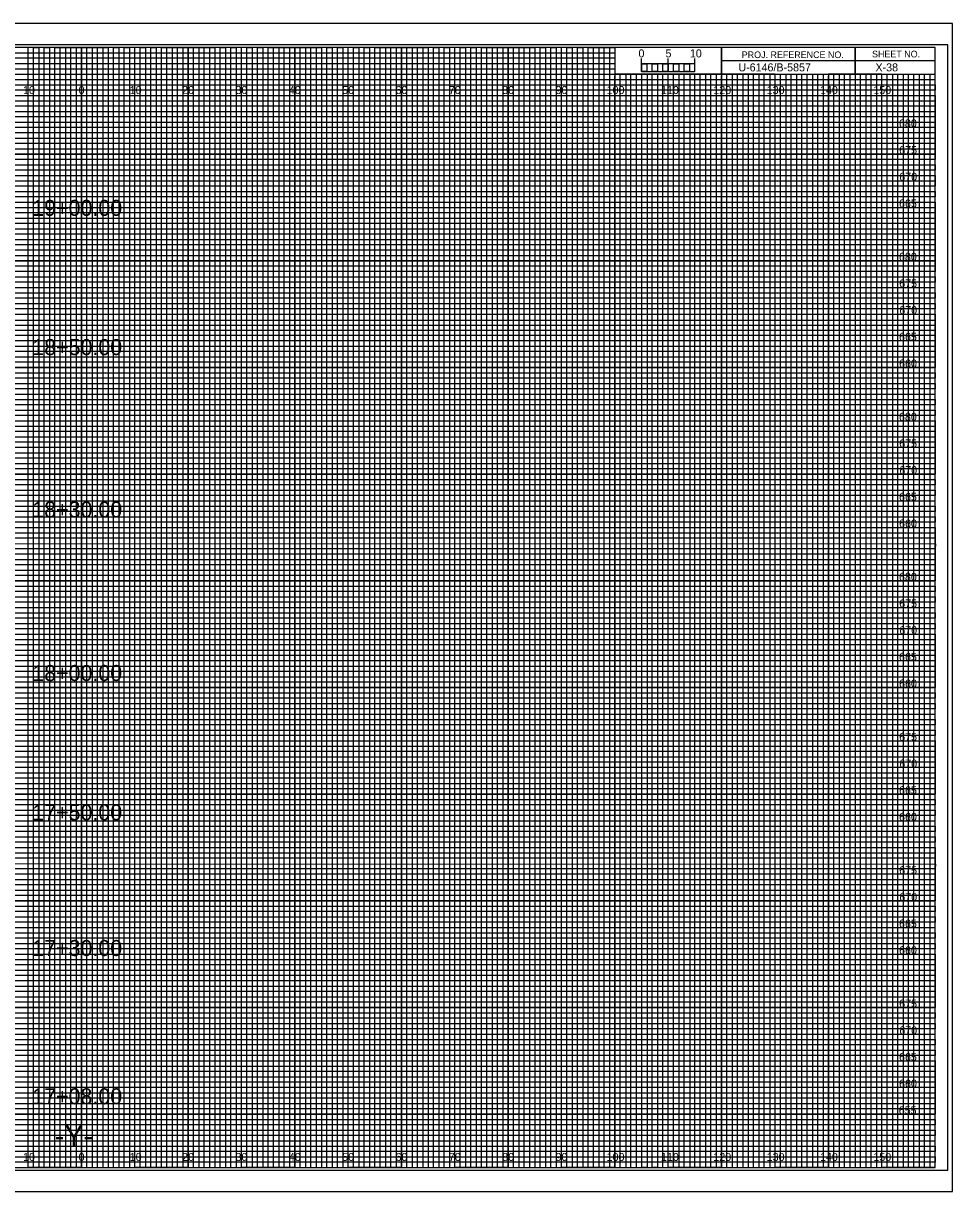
# Model space of a CAD drawing. Extents: x -13 to 323, y 655 to 874.
# Drawn here: x 149.1 to 323.3, y 655.5 to 874.5 of the extents above; entities that cross this region are included whole.
import ezdxf

# ---------------------------------------------------------------- set-up
doc = ezdxf.new("R2010")
doc.units = 0
for name, color, linetype in [('Exist Cross Section Cell', 7, 'Continuous'), ('Exist XS Center Line Elevation Label', 7, 'Continuous'), ('Exist XS Ground Line', 7, 'Continuous'), ('Prop XS Dump Level', 7, 'Continuous'), ('Prop XS EOT Tick Mark', 7, 'Continuous'), ('Prop XS Finish Grade', 7, 'Continuous'), ('Prop XS Finish Grade CurbGutter', 7, 'Continuous'), ('Prop XS Finish Grade Earthwork', 7, 'Continuous'), ('Prop XS Finish Grade Pavement', 7, 'Continuous'), ('Prop XS Hydro Elevations', 7, 'Continuous'), ('Prop XS Pvmt Edge Slope', 7, 'Continuous'), ('Prop XS SE Text', 7, 'Continuous'), ('Prop XS Side Slope Text', 7, 'Continuous'), ('Prop XS SS Elevation Text', 7, 'Continuous'), ('Prop XS Subgrade CurbGutter', 7, 'Continuous'), ('Prop XS Subgrade Earthwork', 7, 'Continuous'), ('Scratch_Level_3', 7, 'Continuous')]:
    doc.layers.add(name, color=color, linetype=linetype)

msp = doc.modelspace()

# ---------------------------------------------------------------- linework, layer by layer
at = {"layer": 'Exist Cross Section Cell'}
for points in [[(145, 660), (155, 660), (155, 870), (165, 870), (165, 660), (175, 660), (175, 870), (185, 870), (185, 660), (195, 660), (195, 870), (205, 870), (205, 660), (215, 660), (215, 870), (225, 870), (225, 660), (235, 660), (235, 870), (245, 870), (245, 660), (255, 660), (255, 870), (259.93, 870), (260, 870), (260, 865), (264.99, 865), (264.99, 660), (275, 660), (275, 865), (285, 865), (285, 660), (295, 660), (295, 865), (305, 865), (305, 660), (315, 660), (315, 865)], [(0, 865), (275, 865)], [(0, 845), (320, 845), (320, 855), (0, 855)], [(0, 825), (320, 825), (320, 835), (0, 835)], [(0, 805), (320, 805), (320, 815), (0, 815)], [(0, 785), (320, 785), (320, 795), (0, 795)], [(0, 765), (320, 765), (320, 775), (0, 775)], [(0, 745), (320, 745), (320, 755), (0, 755)], [(0, 725), (320, 725), (320, 735), (0, 735)], [(0, 705), (320, 705), (320, 715), (0, 715)], [(0, 685), (320, 685), (320, 695), (0, 695)], [(0, 665), (320, 665), (320, 675), (0, 675)]]:
    msp.add_lwpolyline(points, dxfattribs=at)
at = {"layer": 'Exist XS Center Line Elevation Label'}
for p, q in [((150, 870), (140, 870)), ((150, 660), (150, 870)), ((170, 870), (160, 870)), ((160, 870), (160, 660)), ((170, 660), (170, 870)), ((190, 870), (180, 870)), ((180, 870), (180, 660)), ((190, 660), (190, 870)), ((210, 870), (200, 870)), ((200, 870), (200, 660)), ((210, 660), (210, 870)), ((230, 870), (220, 870)), ((220, 870), (220, 660)), ((230, 660), (230, 870)), ((250, 870), (240, 870)), ((240, 870), (240, 660)), ((250, 660), (250, 870)), ((260, 870), (260, 660)), ((270, 660), (270, 865)), ((290, 865), (280, 865)), ((280, 865), (280, 660)), ((290, 660), (290, 865)), ((310, 865), (300, 865)), ((300, 865), (300, 660)), ((310, 660), (310, 865)), ((160, 660), (150, 660)), ((180, 660), (170, 660)), ((200, 660), (190, 660)), ((220, 660), (210, 660)), ((240, 660), (230, 660)), ((260, 660), (250, 660)), ((280, 660), (270, 660)), ((300, 660), (290, 660)), ((320, 660), (310, 660)), ((320, 660), (320, 660))]:
    msp.add_line(p, q, dxfattribs=at)
for points in [[(0, 860), (320, 860), (320, 850), (0, 850)], [(0, 840), (320, 840), (320, 830), (0, 830)], [(0, 820), (320, 820), (320, 810), (0, 810)], [(0, 800), (320, 800), (320, 790), (0, 790)], [(0, 780), (320, 780), (320, 770), (0, 770)], [(0, 760), (320, 760), (320, 750), (0, 750)], [(0, 740), (320, 740), (320, 730), (0, 730)], [(0, 720), (320, 720), (320, 710), (0, 710)], [(0, 700), (320, 700), (320, 690), (0, 690)], [(0, 680), (320, 680), (320, 670), (0, 670)]]:
    msp.add_lwpolyline(points, dxfattribs=at)
at = {"layer": 'Prop XS Dump Level'}
for p, q in [((305, 870), (305, 865)), ((305, 865), (305, 870)), ((280, 867.5), (280, 865)), ((320, 867.49), (280, 867.49)), ((280, 865), (320, 865))]:
    msp.add_line(p, q, dxfattribs=at)
for points in [[(320, 870), (0, 870), (0, 660), (320, 660)], [(280, 870), (260, 870), (260, 865.03), (280, 865.03)], [(320, 870), (280, 870), (280, 865), (320, 865)]]:
    msp.add_lwpolyline(points, close=True, dxfattribs=at)
at = {"layer": 'Prop XS Finish Grade Earthwork'}
for p, q in [((150, 660), (150, 870)), ((160, 660), (160, 870)), ((170, 660), (170, 870)), ((180, 660), (180, 870)), ((190, 660), (190, 870)), ((200, 660), (200, 870)), ((210, 660), (210, 870)), ((220, 660), (220, 870)), ((230, 660), (230, 870)), ((240, 660), (240, 870)), ((250, 660), (250, 870)), ((260, 660), (260, 864.69)), ((270, 660), (270, 864.69)), ((280, 660), (280, 864.69)), ((290, 660), (290, 864.69)), ((300, 660), (300, 864.69)), ((310, 660), (310, 864.69)), ((0, 860), (320, 860)), ((0, 850), (320, 850)), ((0, 840), (320, 840)), ((0, 830), (320, 830)), ((0, 820), (320, 820)), ((0, 810), (320, 810)), ((0, 800), (320, 800)), ((0, 790), (320, 790)), ((0, 780), (320, 780)), ((0, 770), (320, 770)), ((0, 760), (320, 760)), ((0, 750), (320, 750)), ((0, 740), (320, 740)), ((0, 730), (320, 730)), ((0, 720), (320, 720)), ((0, 710), (320, 710)), ((0, 700), (320, 700)), ((0, 690), (320, 690)), ((0, 680), (320, 680)), ((0, 670), (320, 670))]:
    msp.add_line(p, q, dxfattribs=at)
at = {"layer": 'Prop XS Hydro Elevations'}
for p, q in [((265, 865.49), (265, 867.9)), ((265, 866.9), (265, 867.9)), ((270, 865.49), (270, 867.9)), ((275, 865.49), (275, 867.9)), ((275, 866.9), (275, 867.9))]:
    msp.add_line(p, q, dxfattribs=at)
for points in [[(275, 866.9), (265, 866.9), (265, 865.49), (275, 865.49)], [(265, 866.9), (266, 866.9), (266, 865.49), (265, 865.49)], [(267, 866.9), (268, 866.9), (268, 865.49), (267, 865.49)], [(269, 866.9), (270, 866.9), (270, 865.49), (269, 865.49)], [(271, 866.9), (272, 866.9), (272, 865.49), (271, 865.49)], [(273, 866.9), (274, 866.9), (274, 865.49), (273, 865.49)]]:
    msp.add_lwpolyline(points, close=True, dxfattribs=at)
at = {"layer": 'Prop XS Pvmt Edge Slope'}
for p, q in [((323.3, 874.5), (-13.4, 874.5)), ((-13.4, 655.5), (323.3, 655.5))]:
    msp.add_line(p, q, dxfattribs=at)
at = {"layer": 'Prop XS SE Text'}
for p, q in [((267, 865), (266.01, 865)), ((266.01, 865), (266.01, 660)), ((267, 660), (267, 865)), ((269, 865), (268, 865)), ((268, 865), (268, 660)), ((269, 660), (269, 865)), ((266.01, 660), (265, 660)), ((268, 660), (267, 660))]:
    msp.add_line(p, q, dxfattribs=at)
for points in [[(150, 660), (151, 660), (151, 870), (152, 870), (152, 660)], [(152, 660), (153, 660), (153, 870), (154, 870), (154, 660)], [(155, 660), (156, 660), (156, 870), (157, 870), (157, 660)], [(157, 660), (158, 660), (158, 870), (159, 870), (159, 660)], [(160, 660), (161, 660), (161, 870), (162, 870), (162, 660)], [(162, 660), (163, 660), (163, 870), (164, 870), (164, 660)], [(165, 660), (166, 660), (166, 870), (167, 870), (167, 660)], [(167, 660), (168, 660), (168, 870), (169, 870), (169, 660)], [(170, 660), (171, 660), (171, 870), (172, 870), (172, 660)], [(172, 660), (173, 660), (173, 870), (174, 870), (174, 660)], [(175, 660), (176, 660), (176, 870), (177, 870), (177, 660)], [(177, 660), (178, 660), (178, 870), (179, 870), (179, 660)], [(180, 660), (181, 660), (181, 870), (182, 870), (182, 660)], [(182, 660), (183, 660), (183, 870), (184, 870), (184, 660)], [(185, 660), (186, 660), (186, 870), (187, 870), (187, 660)], [(187, 660), (188, 660), (188, 870), (189, 870), (189, 660)], [(190, 660), (191, 660), (191, 870), (192, 870), (192, 660)], [(192, 660), (193, 660), (193, 870), (194, 870), (194, 660)], [(195, 660), (196, 660), (196, 870), (197, 870), (197, 660)], [(197, 660), (198, 660), (198, 870), (199, 870), (199, 660)], [(200, 660), (201, 660), (201, 870), (202, 870), (202, 660)], [(202, 660), (203, 660), (203, 870), (204, 870), (204, 660)], [(205, 660), (206, 660), (206, 870), (207, 870), (207, 660)], [(207, 660), (208, 660), (208, 870), (209, 870), (209, 660)], [(210, 660), (211, 660), (211, 870), (212, 870), (212, 660)], [(212, 660), (213, 660), (213, 870), (214, 870), (214, 660)], [(215, 660), (216, 660), (216, 870), (217, 870), (217, 660)], [(217, 660), (218, 660), (218, 870), (219, 870), (219, 660)], [(220, 660), (221, 660), (221, 870), (222, 870), (222, 660)], [(222, 660), (223, 660), (223, 870), (224, 870), (224, 660)], [(225, 660), (226, 660), (226, 870), (227, 870), (227, 660)], [(227, 660), (228, 660), (228, 870), (229, 870), (229, 660)], [(230, 660), (231, 660), (231, 870), (232, 870), (232, 660)], [(232, 660), (233, 660), (233, 870), (234, 870), (234, 660)], [(235, 660), (236, 660), (236, 870), (237, 870), (237, 660)], [(237, 660), (238, 660), (238, 870), (239, 870), (239, 660)], [(240, 660), (241, 660), (241, 870), (242, 870), (242, 660)], [(242, 660), (243, 660), (243, 870), (244, 870), (244, 660)], [(245, 660), (246, 660), (246, 870), (247, 870), (247, 660)], [(247, 660), (248, 660), (248, 870), (249, 870), (249, 660)], [(250, 660), (251, 660), (251, 870), (252, 870), (252, 660)], [(252, 660), (253, 660), (253, 870), (254, 870), (254, 660)], [(255, 660), (256, 660), (256, 870), (257, 870), (257, 660)], [(257, 660), (258, 660), (258, 870), (259, 870), (259, 660)], [(260, 660), (261, 660), (261, 865), (262.02, 865), (262.02, 660)], [(262, 660), (263, 660), (263, 865), (263.99, 865), (263.99, 660)], [(270, 660), (270.98, 660), (270.98, 865), (272, 865), (272, 660)], [(272, 660), (273, 660), (273, 865), (274.05, 865), (274.05, 660)], [(275, 660), (276, 660), (276, 865), (277, 865), (277, 660)], [(277, 660), (278, 660), (278, 865), (279, 865), (279, 660)], [(280, 660), (281, 660), (281, 865), (282, 865), (282, 660)], [(282, 660), (283, 660), (283, 865), (284, 865), (284, 660)], [(285, 660), (286, 660), (286, 865), (287, 865), (287, 660)], [(287, 660), (288, 660), (288, 865), (289, 865), (289, 660)], [(290, 660), (291, 660), (291, 865), (292, 865), (292, 660)], [(292, 660), (293, 660), (293, 865), (294, 865), (294, 660)], [(295, 660), (296, 660), (296, 865), (297, 865), (297, 660)], [(297, 660), (298, 660), (298, 865), (299, 865), (299, 660)], [(300, 660), (301, 660), (301, 865), (302, 865), (302, 660)], [(302, 660), (303, 660), (303, 865), (304, 865), (304, 660)], [(305, 660), (306, 660), (306, 865), (307, 865), (307, 660)], [(307, 660), (308, 660), (308, 865), (309, 865), (309, 660)], [(310, 660), (311, 660), (311, 865), (312, 865), (312, 660)], [(312, 660), (313, 660), (313, 865), (314, 865), (314, 660)], [(315, 660), (316, 660), (316, 865), (317, 865), (317, 660)], [(317, 660), (318, 660), (318, 865), (319, 865), (319, 660)]]:
    msp.add_lwpolyline(points, dxfattribs=at)
at = {"layer": 'Prop XS Side Slope Text'}
msp.add_lwpolyline([(-10.8, 659.5), (322.4, 659.5), (322.4, 870.5), (-10.8, 870.5)], close=True, dxfattribs=at)
at = {"layer": 'Prop XS SS Elevation Text'}
msp.add_lwpolyline([(-13.4, 655.5), (323.3, 655.5), (323.3, 874.5), (-13.4, 874.5)], close=True, dxfattribs=at)
at = {"layer": 'Scratch_Level_3'}
for p, q in [((0, 869), (260, 869)), ((260, 867.98), (0, 867.98)), ((260, 869), (260, 867.98)), ((0, 867), (260, 867)), ((260, 865.89), (0, 865.89)), ((260, 867), (260, 865.89)), ((0, 864), (320, 864))]:
    msp.add_line(p, q, dxfattribs=at)
for points in [[(0, 863), (270, 863), (320, 863), (320, 862), (0, 862)], [(0, 861), (320, 861), (320, 859), (0, 859)], [(0, 858), (320, 858), (320, 857), (0, 856.98)], [(0, 856), (320, 856), (320, 854), (0, 854)], [(0, 853), (320, 853), (320, 852), (0, 852)], [(0, 851), (320, 851), (320, 849), (0, 849)], [(0, 848), (320, 848), (320, 847), (0, 847)], [(0, 846), (320, 846), (320, 844), (0, 844)], [(0, 843), (320, 843), (320, 842), (0, 842)], [(0, 841), (320, 841), (320, 839), (0, 839)], [(0, 838), (320, 838), (320, 837), (0, 837)], [(0, 836), (320, 836), (320, 833.95), (320, 833), (320, 832), (0, 832)], [(0, 834), (320, 834), (320, 833), (0, 833)], [(0, 831), (320, 831), (320, 829), (0, 829.03)], [(0, 829.03), (320, 829), (320, 828), (0, 828)], [(0, 827), (320, 827), (320, 826), (0, 826)], [(0, 824), (320, 824), (320, 823), (0, 823)], [(0, 822), (320, 822), (320, 821), (0, 821)], [(-0.07, 818.89), (320, 818.89), (320, 817.88), (-0.07, 817.88)], [(0, 817), (320, 817), (320, 816), (0, 816)], [(0, 814), (320, 814), (320, 813), (0, 813)], [(0, 812), (320, 812), (320, 811), (0, 811)], [(0, 809), (320, 809), (320, 808), (0, 808)], [(0, 807), (320, 807), (320, 806), (0, 806)], [(0, 804), (320, 804), (320, 803), (0, 803)], [(0, 802), (320, 802), (320, 801), (0, 801)], [(0, 799), (320, 799), (319.99, 797.98), (0, 798)], [(0, 797), (320, 797), (320, 796), (0, 796)], [(0, 794), (320, 794), (320, 793), (0, 793)], [(0, 792), (320, 792), (320, 791), (0, 791)], [(0, 789), (320, 789), (320, 788), (0, 788)], [(0, 787), (320, 787), (320, 786), (0, 786)], [(0, 784), (320, 784), (320, 783), (0, 783)], [(0, 782), (320, 782), (320, 781), (0, 781)], [(0, 779), (320, 779), (320, 778), (0, 778)], [(0, 776.99), (320.07, 776.91), (320, 776), (0, 776)], [(0, 774), (320, 774), (320, 773), (0, 773)], [(0, 772), (320, 772), (320, 771), (0, 771)], [(0, 769), (320, 769), (320, 768), (0, 768)], [(0, 767), (320, 767), (320, 766), (0, 766)], [(0, 764), (320, 764), (320, 763), (0, 763)], [(0, 762), (320, 762), (320, 761), (0, 761)], [(0, 759), (320, 759), (320, 758), (0, 758)], [(0, 757), (320, 757), (320, 756), (0, 756)], [(0, 754), (320, 754), (320, 753), (0, 753)], [(0, 752), (320, 752), (320, 751), (0, 751)], [(0, 749), (320, 749), (320, 748), (0, 748)], [(0, 747), (320, 747), (320, 746), (0, 746)], [(0, 744), (320, 744), (320, 743), (0, 743)], [(0, 742), (320, 742), (320, 741), (0, 741)], [(0, 739), (320, 739), (319.99, 737.98), (0, 738)], [(0, 737), (320, 737), (320, 736), (0, 736)], [(0, 734), (320, 734), (320, 733), (0, 733)], [(0, 732), (320, 732), (320, 731), (0, 731)], [(0, 729), (320, 729), (320, 728), (0, 728)], [(0, 727), (320, 727), (320, 726), (0, 726)], [(0, 724), (320, 724), (320, 723), (0, 723)], [(0, 722), (320, 722), (320, 721), (0, 721)], [(0, 719), (320, 719), (320, 718), (0, 718)], [(0, 716.99), (320.07, 716.91), (320, 716), (0, 716)], [(0, 714), (320, 714), (320, 713), (0, 713)], [(0, 712), (320, 712), (320, 711), (0, 711)], [(0, 709), (320, 709), (320, 708), (0, 708)], [(0, 707), (320, 707), (320, 706), (0, 706)], [(0, 704), (320, 704), (320, 703), (0, 703)], [(0, 702), (320, 702), (320, 701), (0, 701)], [(0, 699), (320, 699), (320, 698), (0, 698)], [(0, 697), (320, 697), (320, 696), (0, 696)], [(0, 694), (320, 694), (320, 693), (0, 693)], [(0, 692), (320, 692), (320, 691), (0, 691)], [(0, 689), (320, 689), (320, 688), (0, 688)], [(0, 687), (320, 687), (320, 686), (0, 686)], [(0, 684), (320, 684), (320, 683), (0, 683)], [(0, 682), (320, 682), (320, 681), (0, 681)], [(0, 679), (320, 679), (320, 678), (0, 678)], [(0, 677), (320, 677), (320, 676), (0, 676)], [(0, 674), (320, 674), (320, 673), (0, 673)], [(0, 672), (320, 672), (320, 671), (0, 671)], [(0, 669), (320, 669), (320, 668), (0, 668)], [(0, 667), (320, 667), (320, 666), (0, 666)], [(0, 664), (320, 664), (320, 663), (0, 663)], [(0, 662), (320, 662), (320, 661), (0, 661)]]:
    msp.add_lwpolyline(points, dxfattribs=at)

# ---------------------------------------------------------------- texts
at = {"layer": 'Exist XS Ground Line'}
for s, p in [('10', (149.04, 861.25)), ('0', (159.45, 861.25)), ('0', (159.45, 861.25)), ('10', (169.04, 861.25)), ('20', (178.86, 861.25)), ('30', (188.86, 861.25)), ('40', (198.86, 861.25)), ('50', (208.86, 861.25)), ('60', (218.86, 861.25)), ('70', (228.86, 861.25)), ('80', (238.86, 861.25)), ('90', (248.86, 861.25)), ('100', (258.44, 861.25)), ('110', (268.62, 861.25)), ('120', (278.44, 861.25)), ('130', (288.44, 861.25)), ('140', (298.44, 861.25)), ('150', (308.44, 861.25)), ('10', (149.04, 661.25)), ('0', (159.45, 661.25)), ('0', (159.45, 661.25)), ('10', (169.04, 661.25)), ('20', (178.86, 661.25)), ('30', (188.86, 661.25)), ('40', (198.86, 661.25)), ('50', (208.86, 661.25)), ('60', (218.86, 661.25)), ('70', (228.86, 661.25)), ('80', (238.86, 661.25)), ('90', (248.86, 661.25)), ('100', (258.44, 661.25)), ('110', (268.62, 661.25)), ('120', (278.44, 661.25)), ('130', (288.44, 661.25)), ('140', (298.44, 661.25)), ('150', (308.44, 661.25))]:
    msp.add_text(s, height=1.5, dxfattribs=at).set_placement(p)
at = {"layer": 'Prop XS Dump Level'}
for s, p in [('PROJ. REFERENCE NO.', (283.77, 867.99)), ('SHEET NO.', (308.19, 868.12))]:
    msp.add_text(s, height=1.25, dxfattribs=at).set_placement(p)
at = {"layer": 'Prop XS EOT Tick Mark'}
msp.add_text('-Y-', height=4, dxfattribs=at).set_placement((155, 664))
at = {"layer": 'Prop XS Finish Grade'}
for s, p in [('680', (313.24, 855)), ('675', (313.28, 850)), ('670', (313.3, 845)), ('665', (313.25, 840)), ('680', (313.24, 830)), ('675', (313.28, 825)), ('670', (313.3, 820)), ('665', (313.25, 815)), ('660', (313.26, 810)), ('680', (313.24, 800)), ('675', (313.28, 795)), ('670', (313.3, 790)), ('665', (313.25, 785)), ('660', (313.26, 780)), ('680', (313.24, 770)), ('675', (313.28, 765)), ('670', (313.3, 760)), ('665', (313.25, 755)), ('660', (313.26, 750)), ('675', (313.28, 740)), ('670', (313.3, 735)), ('665', (313.25, 730)), ('660', (313.26, 725)), ('675', (313.28, 715)), ('670', (313.3, 710)), ('665', (313.25, 705)), ('660', (313.26, 700)), ('675', (313.28, 690)), ('670', (313.3, 685)), ('665', (313.25, 680)), ('660', (313.26, 675)), ('655', (313.2, 670))]:
    msp.add_text(s, height=1.5, dxfattribs=at).set_placement(p)
at = {"layer": 'Prop XS Finish Grade CurbGutter'}
msp.add_text('U-6146/B-5857', height=1.5, dxfattribs=at).set_placement((283.13, 865.5))
at = {"layer": 'Prop XS Finish Grade Pavement'}
for s, p in [('5', (269.47, 868.12)), ('10', (274.04, 868.12))]:
    msp.add_text(s, height=1.5, dxfattribs=at).set_placement(p)
at = {"layer": 'Prop XS Hydro Elevations'}
msp.add_text('0', height=1.5, dxfattribs=at).set_placement((264.41, 868.12))
at = {"layer": 'Prop XS Subgrade CurbGutter'}
msp.add_text('X-38', height=1.5, dxfattribs=at).set_placement((308.83, 865.5))
at = {"layer": 'Prop XS Subgrade Earthwork'}
for s, p in [('19+00.00', (150.77, 838.41)), ('18+50.00', (150.77, 812.31)), ('18+30.00', (150.77, 781.87)), ('18+00.00', (150.77, 751.22)), ('17+50.00', (150.77, 725.1)), ('17+30.00', (150.77, 699.67)), ('17+08.00', (150.77, 671.87))]:
    msp.add_text(s, height=3, dxfattribs=at).set_placement(p)

doc.saveas('drawing.dxf')
